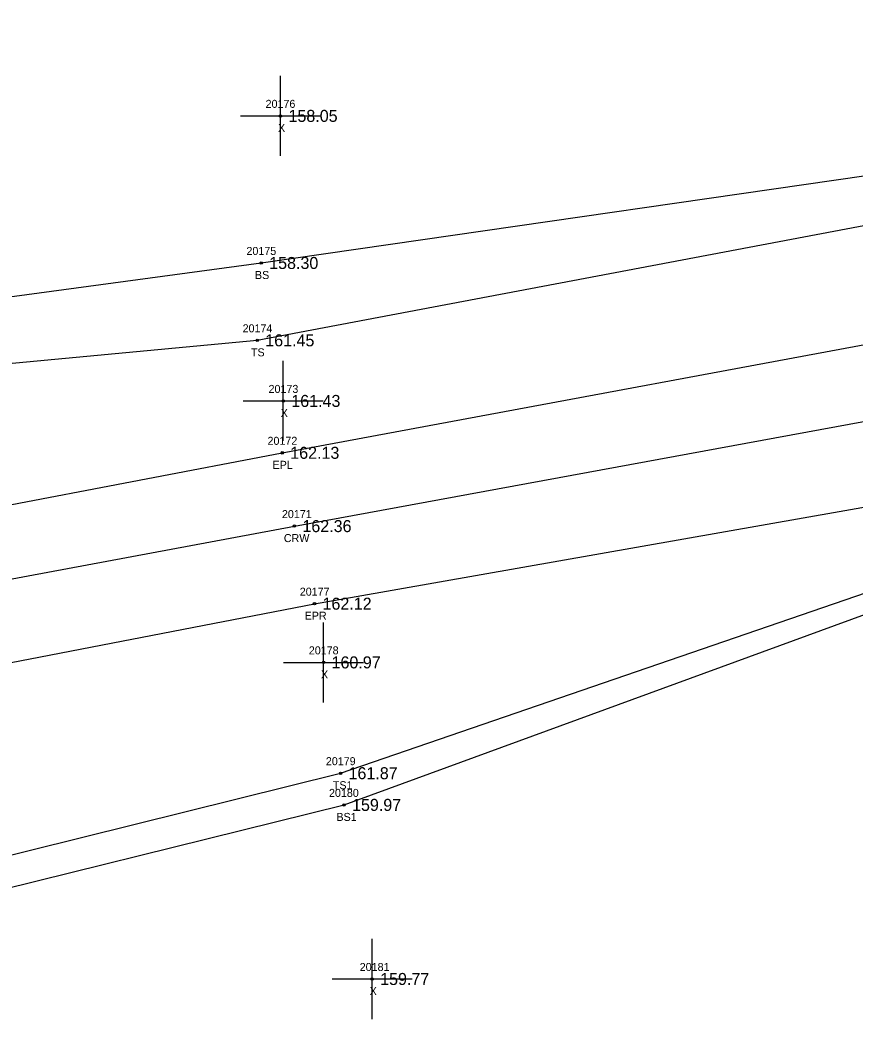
# Model space of a CAD drawing. Extents: x 2381545 to 2382928, y 1029933 to 1030589.
# Drawn here: x 2382309.6 to 2382413.9, y 1030336.2 to 1030461 of the extents above; entities that cross this region are included whole.
import ezdxf

# ---------------------------------------------------------------- set-up
doc = ezdxf.new("R2010")
doc.units = 0
for name, color, linetype in [('RD_DTM_BkLn1', 7, 'Continuous'), ('RD_DTM_BkLn2', 7, 'Continuous'), ('RD_DTM_BkLn_txCode', 7, 'Continuous'), ('RD_EX_Misc', 7, 'Continuous'), ('RD_EX_Misc_txCode', 7, 'Continuous'), ('RD_EX_Road', 7, 'Continuous'), ('RD_EX_Road_txCode', 7, 'Continuous'), ('RD_EX_TX_Misc_ELEV', 7, 'Continuous'), ('RD_EX_TX_Road_ELEV', 7, 'Continuous'), ('RD_HC_Survey_ELEV', 7, 'Continuous'), ('RD_HC_Survey_txCode', 7, 'Continuous'), ('RD_SMD_Locator', 7, 'Continuous')]:
    doc.layers.add(name, color=color, linetype=linetype)

msp = doc.modelspace()

# ---------------------------------------------------------------- linework, layer by layer
at = {"layer": 'RD_DTM_BkLn1'}
msp.add_lwpolyline([(2382237.83, 1030377.97), (2382343.9, 1030397.77), (2382436.97, 1030414.87), (2382557.72, 1030437.27), (2382666.29, 1030458.08), (2382780.92, 1030480.13), (2382908.6, 1030503.95)], dxfattribs=at)
at = {"layer": 'RD_DTM_BkLn2'}
for points in [[(2382228.76, 1030407.08), (2382256.33, 1030426.45), (2382278.98, 1030422.43), (2382339.75, 1030430.63), (2382431.47, 1030443.9), (2382462.65, 1030443.42), (2382466.62, 1030439.12)], [(2382235.13, 1030386.42), (2382230.84, 1030394.95), (2382233.48, 1030405.21), (2382255.02, 1030418.7), (2382277.57, 1030415.22), (2382339.26, 1030420.97), (2382433.29, 1030438.78), (2382461.79, 1030441.66), (2382466.62, 1030439.12)], [(2382241.1, 1030367.72), (2382237.31, 1030356.38), (2382242.21, 1030353.56), (2382262.35, 1030353.01), (2382291.43, 1030352.47), (2382349.66, 1030366.91), (2382440.08, 1030397.96)], [(2382240.51, 1030349.49), (2382260.46, 1030337.58), (2382294.55, 1030349.23), (2382350.1, 1030362.95), (2382424.24, 1030390.04)]]:
    msp.add_lwpolyline(points, dxfattribs=at)
at = {"layer": 'RD_EX_Misc'}
for p, q in [((2382342.16, 1030444), (2382342.16, 1030454)), ((2382337.16, 1030449), (2382347.16, 1030449)), ((2382342.51, 1030408.4), (2382342.51, 1030418.4)), ((2382337.51, 1030413.4), (2382347.51, 1030413.4)), ((2382347.54, 1030375.75), (2382347.54, 1030385.75)), ((2382342.54, 1030380.75), (2382352.54, 1030380.75)), ((2382353.61, 1030336.21), (2382353.61, 1030346.21)), ((2382348.61, 1030341.21), (2382358.61, 1030341.21))]:
    msp.add_line(p, q, dxfattribs=at)
at = {"layer": 'RD_EX_Road'}
for points in [[(2382237.83, 1030377.97), (2382235.13, 1030386.42), (2382342.38, 1030406.92), (2382435.08, 1030424.16), (2382555.51, 1030447.01), (2382663.83, 1030467.83), (2382778.84, 1030489.45), (2382906.57, 1030513.81)], [(2382237.83, 1030377.97), (2382241.1, 1030367.72), (2382346.41, 1030388.08), (2382437.98, 1030404.17), (2382559.51, 1030427.48), (2382667.4, 1030448.54), (2382782.14, 1030469.8), (2382910.48, 1030494.44)]]:
    msp.add_lwpolyline(points, dxfattribs=at)
at = {"layer": 'RD_SMD_Locator'}
for centre in [(2382342.16, 1030449), (2382339.75, 1030430.63), (2382339.26, 1030420.97), (2382342.51, 1030413.4), (2382342.38, 1030406.92), (2382343.9, 1030397.77), (2382346.41, 1030388.08), (2382347.54, 1030380.75), (2382349.66, 1030366.91), (2382350.1, 1030362.95), (2382353.61, 1030341.21)]:
    msp.add_circle(centre, 0.15, dxfattribs=at)

# ---------------------------------------------------------------- texts
at = {"layer": 'RD_DTM_BkLn_txCode'}
for s, p in [('20175', (2382337.91, 1030431.63)), ('BS', (2382338.97, 1030428.63)), ('20174', (2382337.43, 1030421.97)), ('TS', (2382338.47, 1030418.97)), ('20179', (2382347.83, 1030367.91)), ('20180', (2382348.22, 1030363.95)), ('TS1', (2382348.7, 1030364.91)), ('BS1', (2382349.15, 1030360.95))]:
    msp.add_text(s, height=1, dxfattribs=at).set_placement(p)
at = {"layer": 'RD_EX_Misc_txCode'}
for s, p in [('20176', (2382340.3, 1030450)), ('X', (2382341.85, 1030447)), ('20173', (2382340.67, 1030414.4)), ('X', (2382342.19, 1030411.4)), ('20178', (2382345.7, 1030381.75)), ('X', (2382347.22, 1030378.75)), ('20181', (2382352.06, 1030342.21)), ('X', (2382353.3, 1030339.21))]:
    msp.add_text(s, height=1, dxfattribs=at).set_placement(p)
at = {"layer": 'RD_EX_Road_txCode'}
for s, p in [('20172', (2382340.54, 1030407.92)), ('EPL', (2382341.17, 1030404.92)), ('20177', (2382344.57, 1030389.08)), ('EPR', (2382345.18, 1030386.08))]:
    msp.add_text(s, height=1, dxfattribs=at).set_placement(p)
at = {"layer": 'RD_EX_TX_Misc_ELEV'}
for s, p in [('158.05', (2382343.16, 1030448.25)), ('158.30', (2382340.75, 1030429.88)), ('161.45', (2382340.26, 1030420.22)), ('161.43', (2382343.51, 1030412.65)), ('160.97', (2382348.54, 1030380)), ('161.87', (2382350.66, 1030366.16)), ('159.97', (2382351.1, 1030362.2)), ('159.77', (2382354.61, 1030340.46))]:
    msp.add_text(s, height=1.5, dxfattribs=at).set_placement(p)
at = {"layer": 'RD_EX_TX_Road_ELEV'}
for s, p in [('162.13', (2382343.38, 1030406.17)), ('162.12', (2382347.41, 1030387.33))]:
    msp.add_text(s, height=1.5, dxfattribs=at).set_placement(p)
at = {"layer": 'RD_HC_Survey_ELEV'}
msp.add_text('162.36', height=1.5, dxfattribs=at).set_placement((2382344.9, 1030397.02))
at = {"layer": 'RD_HC_Survey_txCode'}
for s, p in [('20171', (2382342.34, 1030398.77)), ('CRW', (2382342.58, 1030395.77))]:
    msp.add_text(s, height=1, dxfattribs=at).set_placement(p)

doc.saveas('drawing.dxf')
